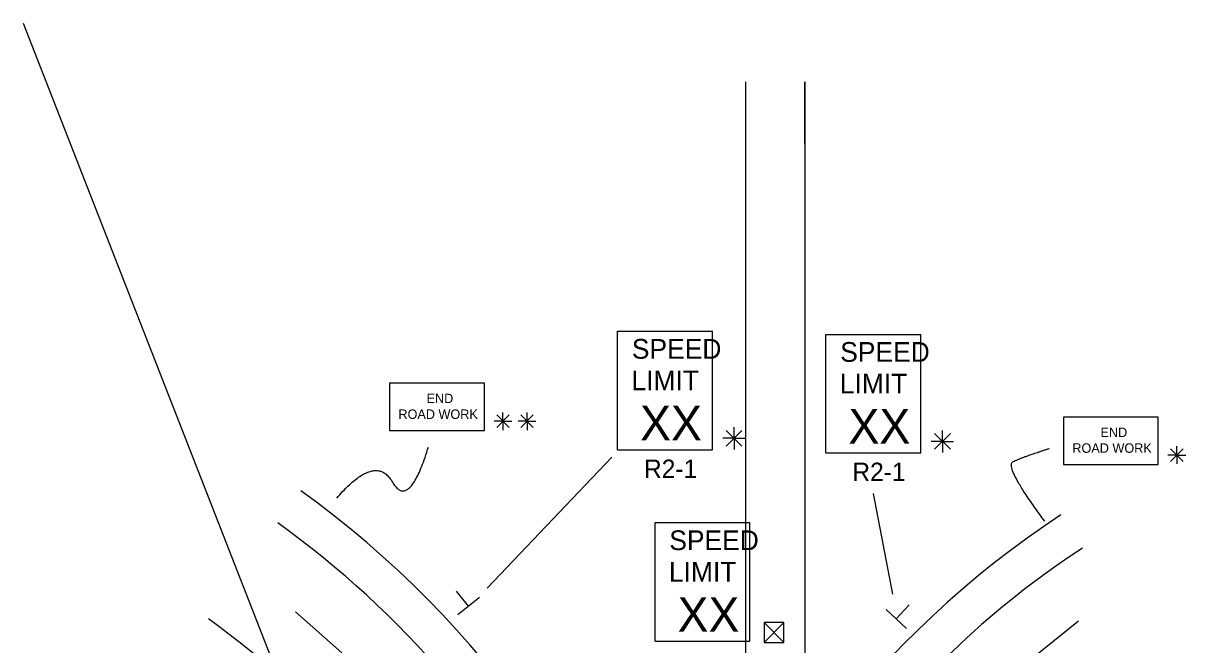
# Model space of a CAD drawing. Extents: x 16486 to 19505, y 5576 to 6998.
# Drawn here: x 16688.1 to 17158.9, y 6745.9 to 6997.8 of the extents above; entities that cross this region are included whole.
import ezdxf

# ---------------------------------------------------------------- set-up
doc = ezdxf.new("R2010")
doc.units = 0
for name, color, linetype in [('ALI_LEGAL_EX', 7, 'Continuous'), ('PAVT_EDGE_EX', 7, 'Continuous'), ('TRAFFIC_SIGNS_PR', 7, 'Continuous'), ('TYPICAL_TEXT_DIMEN_PR', 7, 'Continuous')]:
    doc.layers.add(name, color=color, linetype=linetype)

msp = doc.modelspace()

# ---------------------------------------------------------------- linework, layer by layer
at = {"layer": 'ALI_LEGAL_EX'}
for p, q in [((16688.08, 6997.81), (16910.11, 6429.44)), ((16980.68, 6974.12), (16980.68, 6155.98)), ((17004.68, 6974.12), (17004.68, 6155.98)), ((16980.68, 6922.21), (16980.68, 6058.3)), ((17004.68, 6922.21), (17004.68, 6058.3))]:
    msp.add_line(p, q, dxfattribs=at)
for points in [[(17004.68, 6949.12), (17004.68, 6974.12)], [(16817.07, 6742.72), (16798.4, 6759.35)], [(17096.1, 6739.95), (17115.56, 6755.65)]]:
    msp.add_lwpolyline(points, dxfattribs=at)
at = {"layer": 'PAVT_EDGE_EX'}
for centre, radius, start, end in [((16564.4, 6480.53), 404, 15.917, 54.2283), ((16564.4, 6480.53), 388, 0, 54.2283), ((17316.4, 6480.53), 380, 123.1879, 163.0483), ((17316.4, 6480.53), 364, 123.1879, 180), ((16564.4, 6480.53), 340, 0, 54.2283)]:
    msp.add_arc(centre, radius, start, end, dxfattribs=at)
at = {"layer": 'TRAFFIC_SIGNS_PR'}
for p, q in [((16928.82, 6873), (16967.22, 6873)), ((16928.82, 6825), (16928.82, 6873)), ((16967.22, 6825), (16967.22, 6873)), ((17013.23, 6871.74), (17051.63, 6871.74)), ((17013.23, 6823.74), (17013.23, 6871.74)), ((17051.63, 6823.74), (17051.63, 6871.74)), ((16928.82, 6825), (16967.22, 6825)), ((17013.23, 6823.74), (17051.63, 6823.74)), ((16944, 6795.43), (16982.4, 6795.43)), ((16944, 6747.43), (16944, 6795.43)), ((16982.4, 6747.43), (16982.4, 6795.43)), ((16944, 6747.43), (16982.4, 6747.43))]:
    msp.add_line(p, q, dxfattribs=at)
for points in [[(16836.44, 6832.73), (16874.84, 6832.73), (16874.84, 6851.93), (16836.44, 6851.93)], [(17109.42, 6818.98), (17147.82, 6818.98), (17147.82, 6838.18), (17109.42, 6838.18)]]:
    msp.add_lwpolyline(points, close=True, dxfattribs=at)
at = {"layer": 'TYPICAL_TEXT_DIMEN_PR'}
for p, q in [((16879.84, 6839.1), (16884.94, 6834)), ((16884.94, 6839.1), (16879.84, 6834)), ((16882.39, 6836.55), (16882.39, 6840.12)), ((16889.58, 6839.1), (16894.68, 6834)), ((16894.68, 6839.1), (16889.58, 6834)), ((16892.13, 6836.55), (16892.13, 6840.12)), ((16882.39, 6836.55), (16878.76, 6836.55)), ((16882.39, 6836.55), (16884.94, 6836.55)), ((16882.39, 6836.55), (16885.97, 6836.55)), ((16882.39, 6836.55), (16882.39, 6832.95)), ((16892.13, 6836.55), (16888.51, 6836.55)), ((16892.13, 6836.55), (16894.68, 6836.55)), ((16892.13, 6836.55), (16895.72, 6836.55)), ((16892.13, 6836.55), (16892.13, 6832.95)), ((16972.82, 6832.8), (16979.2, 6826.43)), ((16979.2, 6832.8), (16972.82, 6826.43)), ((16976.01, 6829.62), (16976.01, 6834.07)), ((17060.42, 6828.35), (17060.42, 6832.81)), ((16976.01, 6829.62), (16971.48, 6829.62)), ((16976.01, 6829.62), (16979.2, 6829.62)), ((16976.01, 6829.62), (16980.49, 6829.62)), ((16976.01, 6829.62), (16976.01, 6825.12)), ((17060.42, 6828.35), (17055.88, 6828.35)), ((17057.23, 6831.54), (17063.6, 6825.16)), ((17063.6, 6831.54), (17057.23, 6825.16)), ((17060.42, 6828.35), (17063.6, 6828.35)), ((17060.42, 6828.35), (17064.89, 6828.35)), ((17060.42, 6828.35), (17060.42, 6823.85)), ((17157.92, 6825.36), (17152.81, 6820.25)), ((17152.82, 6825.36), (17157.92, 6820.25)), ((17155.36, 6822.8), (17155.36, 6826.37)), ((16926.42, 6822.03), (16875.94, 6768.85)), ((17155.36, 6822.8), (17151.74, 6822.8)), ((17155.36, 6822.8), (17157.92, 6822.8)), ((17155.36, 6822.8), (17158.95, 6822.8)), ((17155.36, 6822.8), (17155.36, 6819.2)), ((17040.24, 6766.41), (17032.44, 6807.29)), ((16868.44, 6761.57), (16863.56, 6767.65)), ((16872.82, 6765.09), (16864.05, 6758.06)), ((17041.66, 6756.39), (17046.96, 6762.1)), ((17045.78, 6752.57), (17037.54, 6760.22)), ((16988.15, 6754.9), (16996.15, 6746.9)), ((16988.15, 6746.9), (16996.15, 6754.9))]:
    msp.add_line(p, q, dxfattribs=at)
msp.add_lwpolyline([(16988.15, 6754.9), (16988.15, 6746.9), (16996.15, 6746.9), (16996.15, 6754.9)], close=True, dxfattribs=at)
for points in [[(16815.05, 6805.35), (16830.8, 6823.7), (16844.29, 6800.22), (16852.21, 6826.08)], [(17101.86, 6795.98), (17085.23, 6818.28), (17092.8, 6822.02), (17103.73, 6825.48)]]:
    msp.add_open_spline(points, degree=2, dxfattribs=at)

# ---------------------------------------------------------------- texts
at = {"layer": 'TRAFFIC_SIGNS_PR'}
for s, height, p in [('SPEED', 8, (16934.59, 6861.86)), ('SPEED', 8, (17018.99, 6860.6)), ('LIMIT', 8, (16934.43, 6849.06)), ('LIMIT', 8, (17018.83, 6847.8)), ('END', 3.831, (16851.44, 6843.86)), ('XX', 14.031, (16937.93, 6828.76)), ('ROAD WORK', 3.831, (16840.05, 6837.47)), ('XX', 14.031, (17022.34, 6827.49)), ('END', 3.831, (17124.42, 6830.11)), ('ROAD WORK', 3.831, (17113.02, 6823.73)), ('R2-1', 7.44, (16939.5, 6813.56)), ('R2-1', 7.44, (17023.9, 6812.3)), ('SPEED', 8, (16949.76, 6784.29)), ('LIMIT', 8, (16949.6, 6771.49)), ('XX', 14.031, (16953.11, 6751.19))]:
    msp.add_text(s, height=height, dxfattribs=at).set_placement(p)

doc.saveas('drawing.dxf')
